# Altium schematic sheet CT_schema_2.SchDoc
size 308 x 312 mm
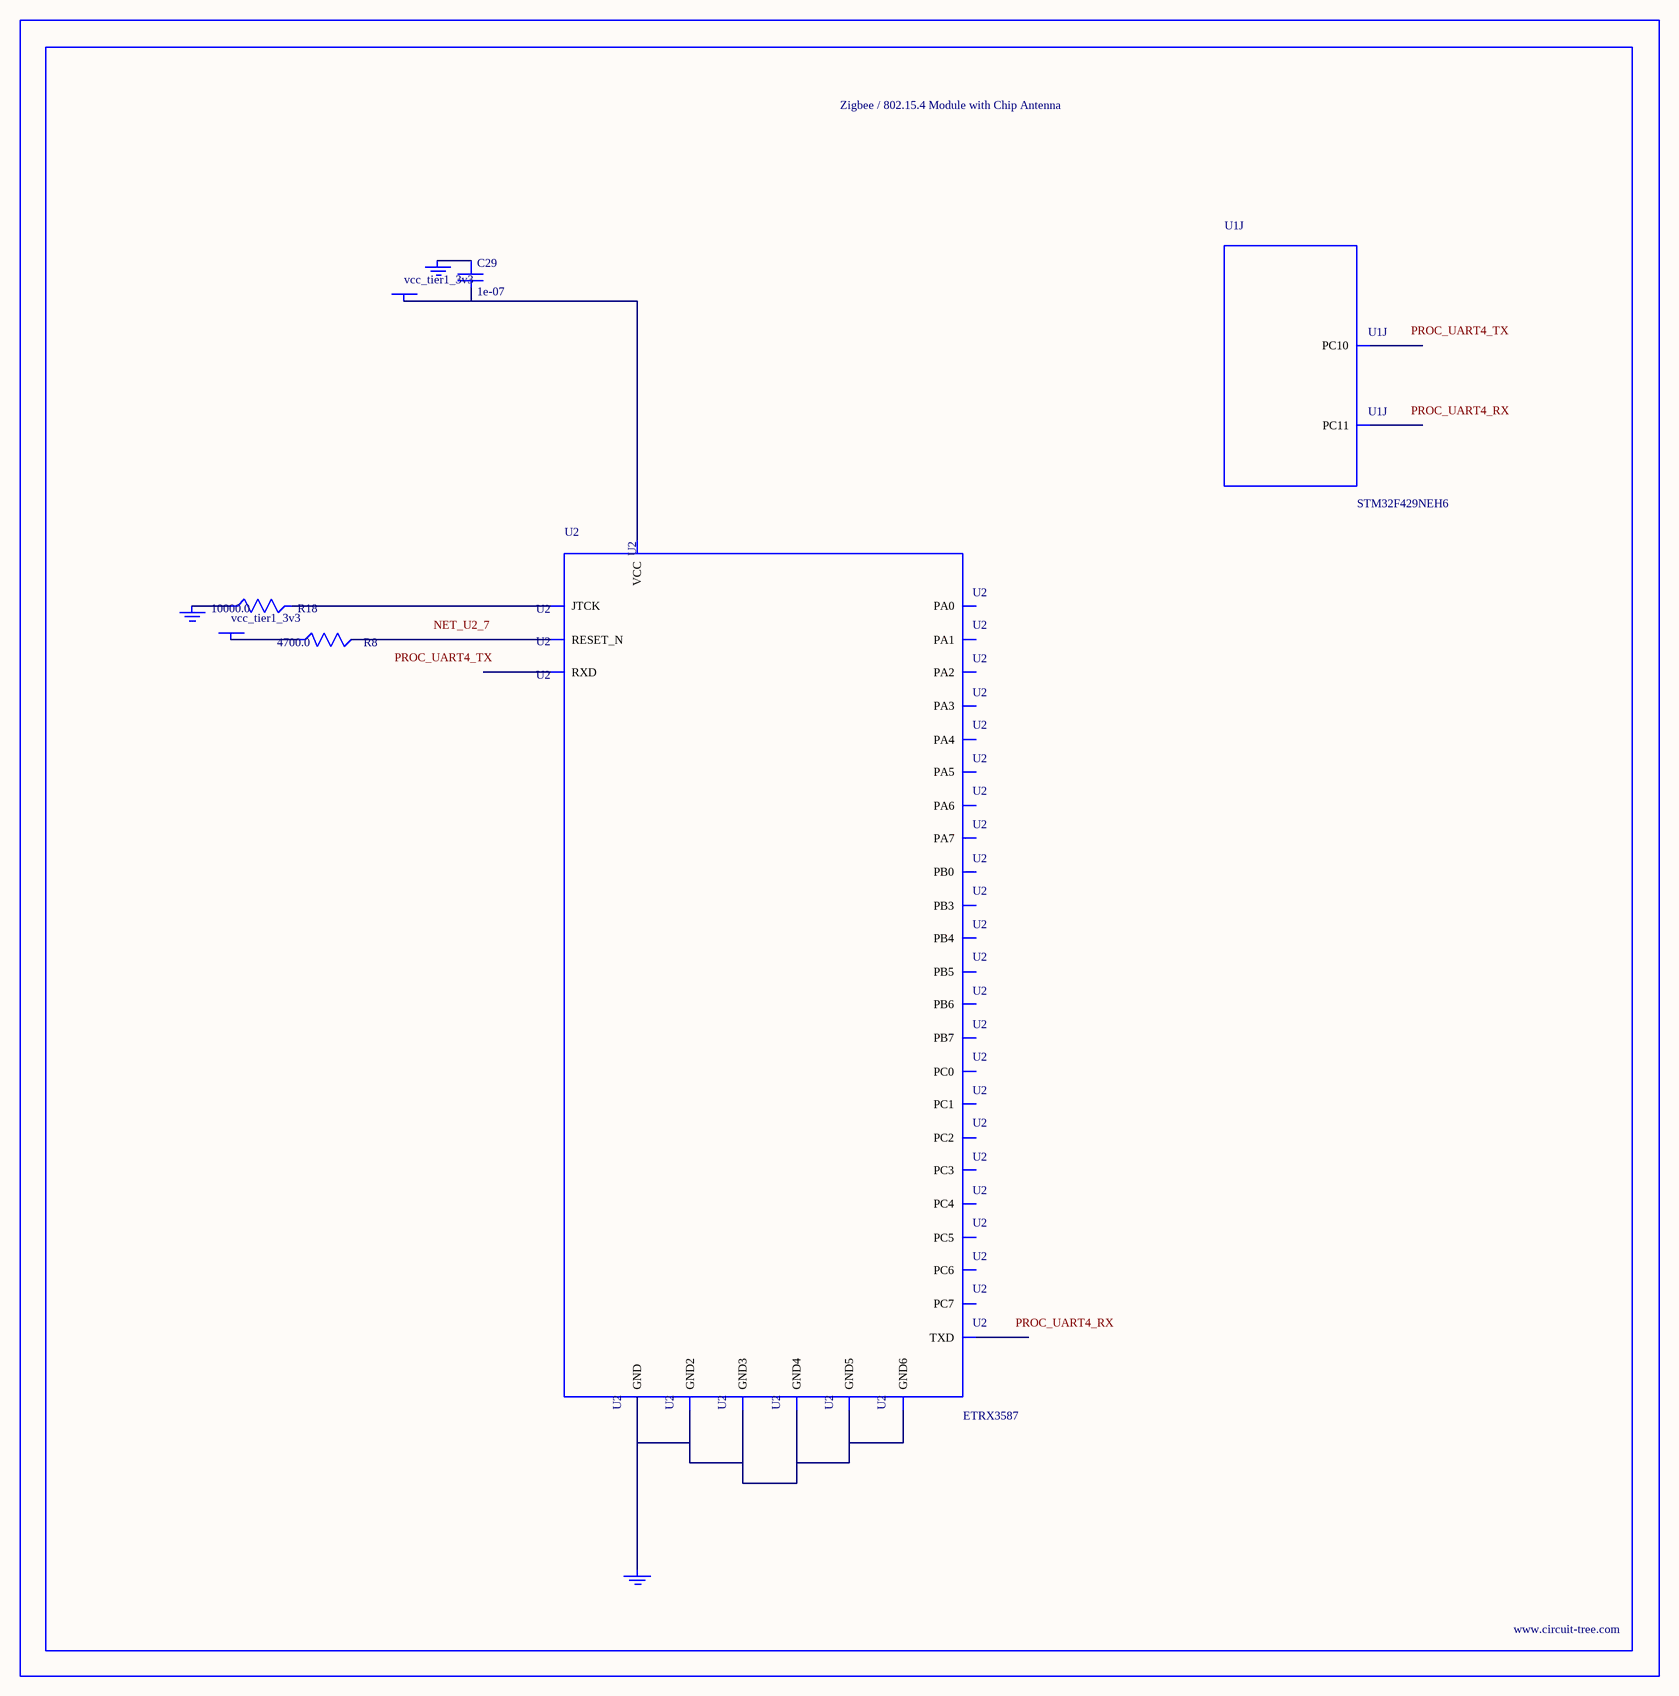
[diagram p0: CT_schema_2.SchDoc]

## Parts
BORDER1  (no value)
C29  1e-07  [C0402]
GND_INSTANCE_1_0  (no value)
GND_INSTANCE_1_1  (no value)
GND_INSTANCE_1_2  (no value)
POWER_INSTANCE_1_0  vcc_tier1_3v3
POWER_INSTANCE_1_1  vcc_tier1_3v3
R8  4700.0  [R0603]
R18  10000.0  [R0603]
U1  STM32F429NEH6  [TFBGA216]  (part J of 17)
U2  ETRX3587  [ETRX3587]

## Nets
NetC29_1: C29.1 GND_INSTANCE_1_1.0(GND)
NetC29_2: C29.2 POWER_INSTANCE_1_0.0(PWR) U2.32(VCC)
NetGND_INSTANCE_1_0_0: GND_INSTANCE_1_0.0(GND) R18.1
NetGND_INSTANCE_1_2_0: GND_INSTANCE_1_2.0(GND) U2.1(GND) U2.13(GND2) U2.19(GND3) U2.20(GND4) U2.31(GND5) U2.33(GND6)
NetPOWER_INSTANCE_1_1_0: POWER_INSTANCE_1_1.0(PWR) R8.1
NetR8_2: R8.2 U2.7(RESET_N)
NetR18_2: R18.2 U2.21(JTCK)

Not connected (* = marked no-connect by the designer): U1 B13(PC11) B14(PC10); U2 2(PC5) 3(PC6) 4(PC7) 5(PA7) 6(PB3) 8(PB4) 9(PA0) 10(PA1) 11(PA2) 12(PA3) 14(PA4) 15(PA5) 16(PA6) 17(TXD) 18(RXD) 22(PC2) 23(PC3) 24(PC4) 25(PB0) 26(PC1) 27(PC0) 28(PB7) 29(PB6) 30(PB5)

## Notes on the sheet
- Labels drawn without touching a wire or pin: NET_U2_7, PROC_UART4_RX, PROC_UART4_TX

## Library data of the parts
BORDER1 = BORDER_PAGE1
C29 = C0402C104K3RACTU
GND_INSTANCE_1_0-GND_INSTANCE_1_2 = GND
POWER_INSTANCE_1_0 POWER_INSTANCE_1_1 = PWR
R8 = RC0603JR-074K7L
R18 = RC0603JR-0710KL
